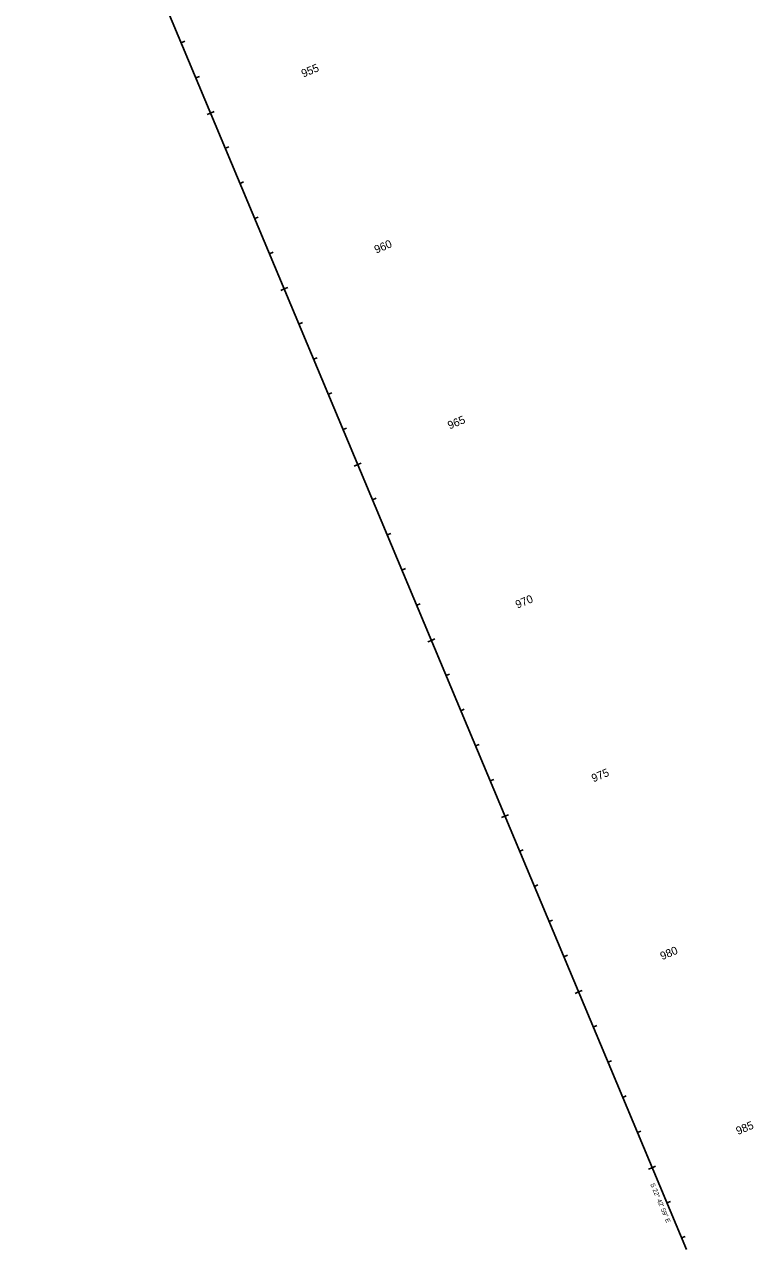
# Model space of a CAD drawing. Extents: x 2819977 to 2827606, y 113942 to 150283.
# Drawn here: x 2821726 to 2823639, y 121230 to 124445 of the extents above; entities that cross this region are included whole.
import ezdxf

# ---------------------------------------------------------------- set-up
doc = ezdxf.new("R2010")
doc.units = 0
doc.layers.add('Roadway-Signs', color=7, linetype='Continuous')
doc.layers.add('Utility-Power', color=7, linetype='Continuous')

msp = doc.modelspace()

# ---------------------------------------------------------------- linework, layer by layer
at = {"layer": 'Utility-Power'}
for p, q in [((2821725.8, 125379.3), (2823462.7, 121230.3)), ((2822137.1, 124396.8), (2822146.3, 124400.7)), ((2822175.7, 124304.6), (2822184.9, 124308.4)), ((2822214.3, 124212.3), (2822205.1, 124208.4)), ((2822214.3, 124212.3), (2822223.5, 124216.2)), ((2822252.9, 124120.1), (2822262.2, 124123.9)), ((2822291.6, 124027.8), (2822300.8, 124031.7)), ((2822330.2, 123935.6), (2822339.4, 123939.4)), ((2822368.8, 123843.3), (2822378, 123847.2)), ((2822407.4, 123751.1), (2822398.2, 123747.2)), ((2822407.4, 123751.1), (2822416.6, 123755)), ((2822446, 123658.9), (2822455.2, 123662.7)), ((2822484.6, 123566.6), (2822493.9, 123570.5)), ((2822523.3, 123474.4), (2822532.5, 123478.2)), ((2822561.9, 123382.1), (2822571.1, 123386)), ((2822600.5, 123289.9), (2822591.3, 123286)), ((2822600.5, 123289.9), (2822609.7, 123293.7)), ((2822639.1, 123197.6), (2822648.3, 123201.5)), ((2822677.7, 123105.4), (2822687, 123109.3)), ((2822716.3, 123013.2), (2822725.6, 123017)), ((2822755, 122920.9), (2822764.2, 122924.8)), ((2822793.6, 122828.7), (2822802.8, 122832.5)), ((2822793.6, 122828.7), (2822784.4, 122824.8)), ((2822832.2, 122736.4), (2822841.4, 122740.3)), ((2822870.8, 122644.2), (2822880, 122648)), ((2822909.4, 122551.9), (2822918.7, 122555.8)), ((2822948, 122459.7), (2822957.3, 122463.6)), ((2822986.7, 122367.5), (2822977.4, 122363.6)), ((2822986.7, 122367.5), (2822995.9, 122371.3)), ((2823025.3, 122275.2), (2823034.5, 122279.1)), ((2823063.9, 122183), (2823073.1, 122186.8)), ((2823102.5, 122090.7), (2823111.7, 122094.6)), ((2823141.1, 121998.5), (2823150.4, 122002.3)), ((2823179.7, 121906.2), (2823170.5, 121902.4)), ((2823179.7, 121906.2), (2823189, 121910.1)), ((2823218.4, 121814), (2823227.6, 121817.9)), ((2823257, 121721.8), (2823266.2, 121725.6)), ((2823295.6, 121629.5), (2823304.8, 121633.4)), ((2823334.2, 121537.3), (2823343.4, 121541.1)), ((2823372.8, 121445), (2823382.1, 121448.9)), ((2823372.8, 121445), (2823363.6, 121441.2)), ((2823411.4, 121352.8), (2823420.7, 121356.6)), ((2823450.1, 121260.5), (2823459.3, 121264.4))]:
    msp.add_line(p, q, dxfattribs=at)

# ---------------------------------------------------------------- texts
at = {"layer": 'Roadway-Signs'}
msp.add_text('S 22%%d 42\' 59" E', height=12, rotation=292.7163, dxfattribs=at).set_placement((2823367.7, 121401.7))
at = {"layer": 'Utility-Power'}
for s, p in [(' 955', (2822450.3, 124302.4)), (' 960', (2822641.8, 123840.5)), (' 965', (2822834.3, 123379)), (' 970', (2823012.1, 122908.8)), (' 975', (2823211.8, 122453)), (' 980', (2823392, 121986.4)), (' 985', (2823591, 121527.6))]:
    msp.add_text(s, height=21, rotation=22.7163, dxfattribs=at).set_placement(p)

doc.saveas('drawing.dxf')
